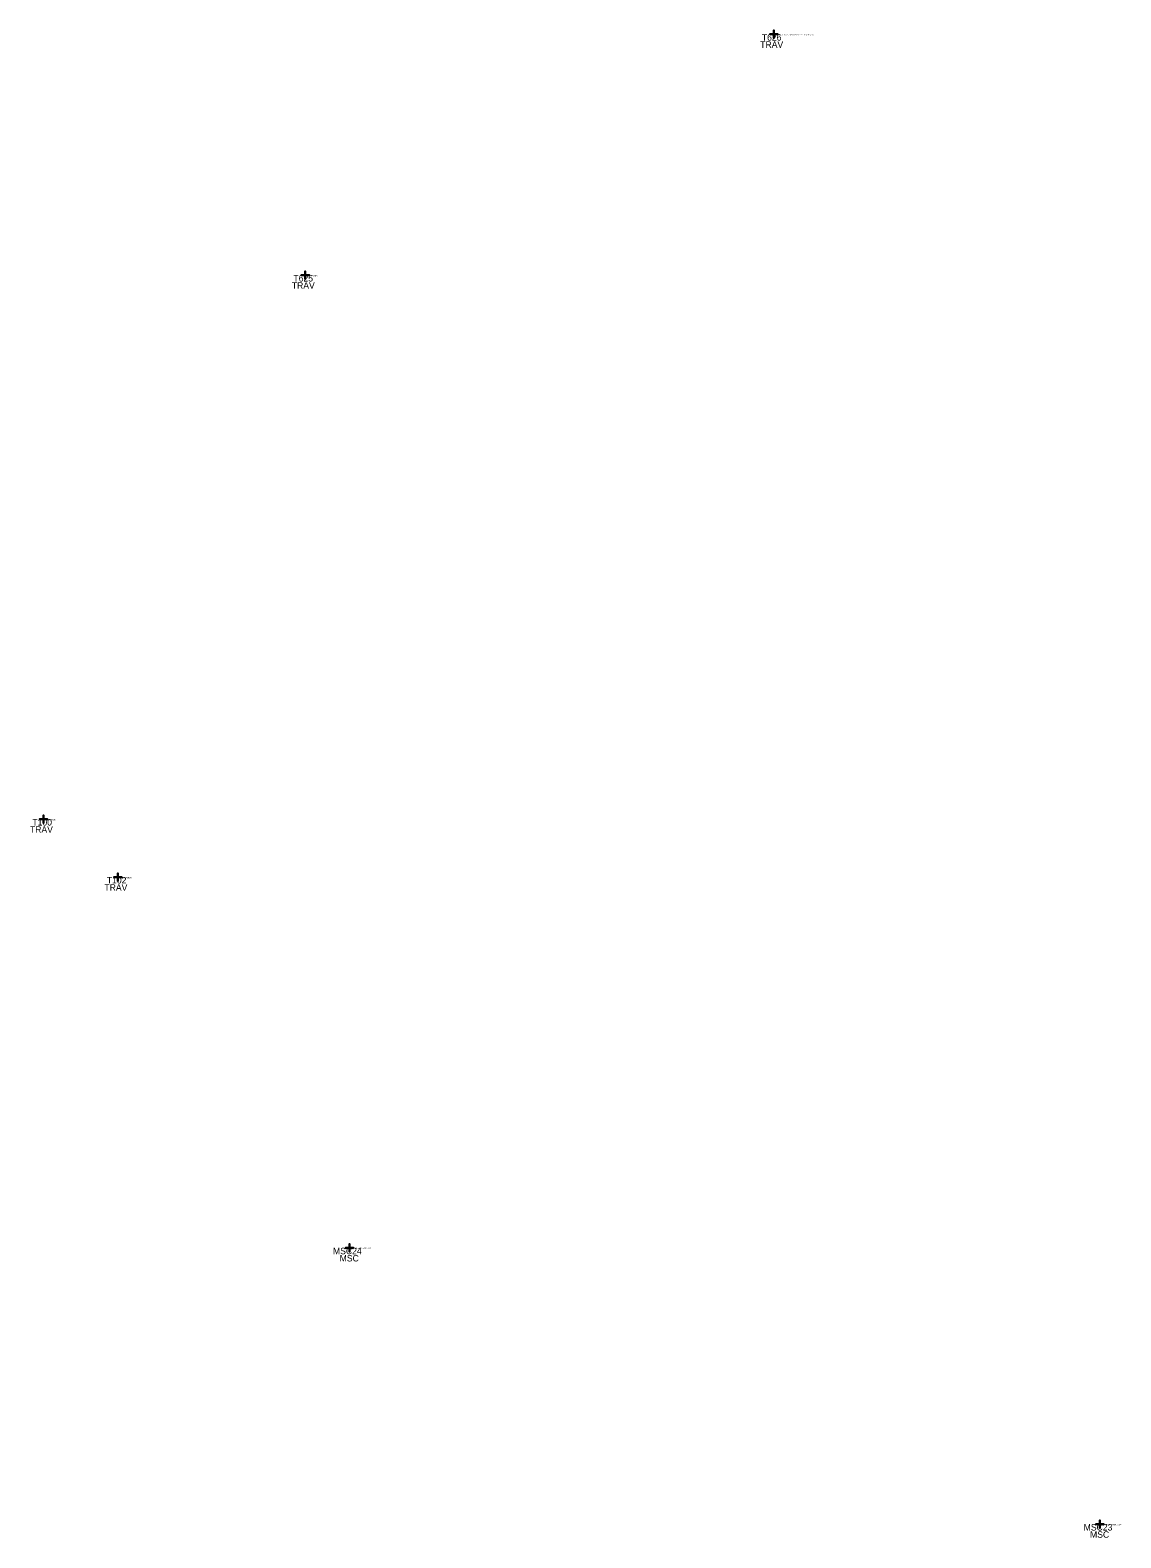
# Model space of a CAD drawing. Extents: x 2342247 to 2353588, y 365809 to 372747.
# Drawn here: x 2349455 to 2350813, y 367197 to 369075 of the extents above; entities that cross this region are included whole.
import ezdxf

# ---------------------------------------------------------------- set-up
doc = ezdxf.new("R2010")
doc.units = 0
for name, color, linetype in [('Level 63', 7, 'Continuous'), ('SV_Control_CP_Code', 7, 'Continuous'), ('SV_Control_CP_Name', 7, 'Continuous'), ('SV_Control_CP_Shot', 7, 'Continuous')]:
    doc.layers.add(name, color=color, linetype=linetype)

msp = doc.modelspace()

# ---------------------------------------------------------------- linework, layer by layer
at = {"layer": 'SV_Control_CP_Shot'}
for points in [[(2350380.6, 369070), (2350380.6, 369075), (2350380.6, 369070), (2350375.6, 369070), (2350380.6, 369070), (2350380.6, 369065), (2350380.6, 369070), (2350385.6, 369070)], [(2349797.4, 368770), (2349797.4, 368775), (2349797.4, 368770), (2349792.4, 368770), (2349797.4, 368770), (2349797.4, 368765), (2349797.4, 368770), (2349802.4, 368770)], [(2349471.4, 368092.5), (2349471.4, 368097.5), (2349471.4, 368092.5), (2349466.4, 368092.5), (2349471.4, 368092.5), (2349471.4, 368087.5), (2349471.4, 368092.5), (2349476.4, 368092.5)], [(2349564.1, 368020.3), (2349564.1, 368025.3), (2349564.1, 368020.3), (2349559.1, 368020.3), (2349564.1, 368020.3), (2349564.1, 368015.3), (2349564.1, 368020.3), (2349569.1, 368020.3)], [(2349852.3, 367558.6), (2349852.3, 367563.6), (2349852.3, 367558.6), (2349847.3, 367558.6), (2349852.3, 367558.6), (2349852.3, 367553.6), (2349852.3, 367558.6), (2349857.3, 367558.6)], [(2350786.5, 367214.5), (2350786.5, 367219.5), (2350786.5, 367214.5), (2350781.5, 367214.5), (2350786.5, 367214.5), (2350786.5, 367209.5), (2350786.5, 367214.5), (2350791.5, 367214.5)]]:
    msp.add_lwpolyline(points, close=True, dxfattribs=at)

# ---------------------------------------------------------------- texts
at = {"layer": 'Level 63'}
for s, p in [('ALSO TP13 IN ORIGINAL LEVELS PK IN SIDEWALK', (2350380.6, 369068.5)), ('PK W/WASHER', (2349797.4, 368768.5)), ('PK W/WASHER', (2349471.4, 368091)), ('NAIL W/WASHER', (2349564.1, 368018.8)), ('#5 REBAR W/ PLASTIC CAP', (2349852.3, 367557.1)), ('#5 REBAR W/ PLASTIC CAP', (2350786.5, 367213))]:
    msp.add_text(s, height=1.5, dxfattribs=at).set_placement(p)
at = {"layer": 'SV_Control_CP_Code'}
for s, p in [('TRAV', (2350363.8, 369053)), ('TRAV', (2349780.6, 368753)), ('TRAV', (2349454.6, 368075.5)), ('TRAV', (2349547.3, 368003.3)), ('MSC', (2349840.2, 367541.6)), ('MSC', (2350774.4, 367197.5))]:
    msp.add_text(s, height=8, dxfattribs=at).set_placement(p)
at = {"layer": 'SV_Control_CP_Name'}
for s, p in [('T626', (2350365.8, 369062)), ('T625', (2349782.6, 368762)), ('T100', (2349457.6, 368084.5)), ('T102', (2349550.3, 368012.3)), ('MSC24', (2349831.9, 367550.6)), ('MSC23', (2350766.5, 367206.5))]:
    msp.add_text(s, height=8, dxfattribs=at).set_placement(p)

doc.saveas('drawing.dxf')
